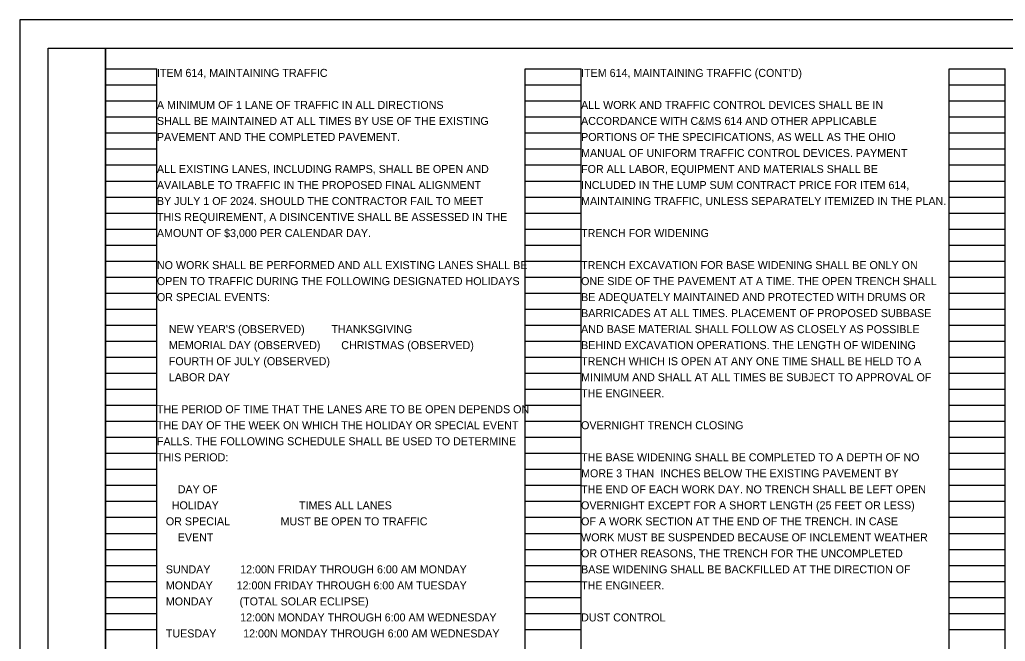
# Model space of a CAD drawing. Extents: x 0 to 34, y 0 to 22.
# Drawn here: x 0 to 17.24, y 11.13 to 22 of the extents above; entities that cross this region are included whole.
import ezdxf

# ---------------------------------------------------------------- set-up
doc = ezdxf.new("R2010")
doc.units = 0
for name, color, linetype in [('SC_Scratch1', 7, 'Continuous'), ('SH_Border', 7, 'Continuous'), ('SH_Cut_Line', 7, 'Continuous'), ('SH_Text', 7, 'Continuous')]:
    doc.layers.add(name, color=color, linetype=linetype)

msp = doc.modelspace()

# ---------------------------------------------------------------- linework, layer by layer
at = {"layer": 'SC_Scratch1'}
for p, q in [((1.5, 0.98), (1.5, 21.14)), ((1.5, 21.14), (2.4, 21.14)), ((2.4, 0.98), (2.4, 21.14)), ((8.84, 0.98), (8.84, 21.14)), ((8.84, 21.14), (9.82, 21.14)), ((9.82, 0.98), (9.82, 21.14)), ((16.26, 0.98), (16.26, 21.14)), ((16.26, 21.14), (17.24, 21.14)), ((17.24, 0.98), (17.24, 21.14)), ((1.5, 20.86), (2.4, 20.86)), ((8.84, 20.86), (9.82, 20.86)), ((16.26, 20.86), (17.24, 20.86)), ((1.5, 20.58), (2.4, 20.58)), ((8.84, 20.58), (9.82, 20.58)), ((16.26, 20.58), (17.24, 20.58)), ((1.5, 20.3), (2.4, 20.3)), ((8.84, 20.3), (9.82, 20.3)), ((16.26, 20.3), (17.24, 20.3)), ((1.5, 20.02), (2.4, 20.02)), ((8.84, 20.02), (9.82, 20.02)), ((16.26, 20.02), (17.24, 20.02)), ((1.5, 19.74), (2.4, 19.74)), ((8.84, 19.74), (9.82, 19.74)), ((16.26, 19.74), (17.24, 19.74)), ((1.5, 19.46), (2.4, 19.46)), ((8.84, 19.46), (9.82, 19.46)), ((16.26, 19.46), (17.24, 19.46)), ((1.5, 19.18), (2.4, 19.18)), ((8.84, 19.18), (9.82, 19.18)), ((16.26, 19.18), (17.24, 19.18)), ((1.5, 18.9), (2.4, 18.9)), ((8.84, 18.9), (9.82, 18.9)), ((16.26, 18.9), (17.24, 18.9)), ((1.5, 18.62), (2.4, 18.62)), ((8.84, 18.62), (9.82, 18.62)), ((16.26, 18.62), (17.24, 18.62)), ((1.5, 18.34), (2.4, 18.34)), ((8.84, 18.34), (9.82, 18.34)), ((16.26, 18.34), (17.24, 18.34)), ((1.5, 18.06), (2.4, 18.06)), ((8.84, 18.06), (9.82, 18.06)), ((16.26, 18.06), (17.24, 18.06)), ((1.5, 17.78), (2.4, 17.78)), ((8.84, 17.78), (9.82, 17.78)), ((16.26, 17.78), (17.24, 17.78)), ((1.5, 17.5), (2.4, 17.5)), ((8.84, 17.5), (9.82, 17.5)), ((16.26, 17.5), (17.24, 17.5)), ((1.5, 17.22), (2.4, 17.22)), ((8.84, 17.22), (9.82, 17.22)), ((16.26, 17.22), (17.24, 17.22)), ((1.5, 16.94), (2.4, 16.94)), ((8.84, 16.94), (9.82, 16.94)), ((16.26, 16.94), (17.24, 16.94)), ((1.5, 16.66), (2.4, 16.66)), ((8.84, 16.66), (9.82, 16.66)), ((16.26, 16.66), (17.24, 16.66)), ((1.5, 16.38), (2.4, 16.38)), ((8.84, 16.38), (9.82, 16.38)), ((16.26, 16.38), (17.24, 16.38)), ((1.5, 16.1), (2.4, 16.1)), ((8.84, 16.1), (9.82, 16.1)), ((16.26, 16.1), (17.24, 16.1)), ((1.5, 15.82), (2.4, 15.82)), ((8.84, 15.82), (9.82, 15.82)), ((16.26, 15.82), (17.24, 15.82)), ((1.5, 15.54), (2.4, 15.54)), ((8.84, 15.54), (9.82, 15.54)), ((16.26, 15.54), (17.24, 15.54)), ((1.5, 15.26), (2.4, 15.26)), ((8.84, 15.26), (9.82, 15.26)), ((16.26, 15.26), (17.24, 15.26)), ((1.5, 14.98), (2.4, 14.98)), ((8.84, 14.98), (9.82, 14.98)), ((16.26, 14.98), (17.24, 14.98)), ((1.5, 14.7), (2.4, 14.7)), ((8.84, 14.7), (9.82, 14.7)), ((16.26, 14.7), (17.24, 14.7)), ((1.5, 14.42), (2.4, 14.42)), ((8.84, 14.42), (9.82, 14.42)), ((16.26, 14.42), (17.24, 14.42)), ((1.5, 14.14), (2.4, 14.14)), ((8.84, 14.14), (9.82, 14.14)), ((16.26, 14.14), (17.24, 14.14)), ((1.5, 13.86), (2.4, 13.86)), ((8.84, 13.86), (9.82, 13.86)), ((16.26, 13.86), (17.24, 13.86)), ((1.5, 13.58), (2.4, 13.58)), ((8.84, 13.58), (9.82, 13.58)), ((16.26, 13.58), (17.24, 13.58)), ((1.5, 13.3), (2.4, 13.3)), ((8.84, 13.3), (9.82, 13.3)), ((16.26, 13.3), (17.24, 13.3)), ((1.5, 13.02), (2.4, 13.02)), ((8.84, 13.02), (9.82, 13.02)), ((16.26, 13.02), (17.24, 13.02)), ((1.5, 12.74), (2.4, 12.74)), ((8.84, 12.74), (9.82, 12.74)), ((16.26, 12.74), (17.24, 12.74)), ((1.5, 12.46), (2.4, 12.46)), ((8.84, 12.46), (9.82, 12.46)), ((16.26, 12.46), (17.24, 12.46)), ((1.5, 12.18), (2.4, 12.18)), ((8.84, 12.18), (9.82, 12.18)), ((16.26, 12.18), (17.24, 12.18)), ((1.5, 11.9), (2.4, 11.9)), ((8.84, 11.9), (9.82, 11.9)), ((16.26, 11.9), (17.24, 11.9)), ((1.5, 11.62), (2.4, 11.62)), ((8.84, 11.62), (9.82, 11.62)), ((16.26, 11.62), (17.24, 11.62)), ((1.5, 11.34), (2.4, 11.34)), ((8.84, 11.34), (9.82, 11.34)), ((16.26, 11.34), (17.24, 11.34))]:
    msp.add_line(p, q, dxfattribs=at)
at = {"layer": 'SH_Border'}
for points in [[(0.5, 21.5), (1.5, 21.5), (1.5, 0.5), (0.5, 0.5)], [(1.5, 21.5), (33.5, 21.5), (33.5, 0.5), (1.5, 0.5)]]:
    msp.add_lwpolyline(points, close=True, dxfattribs=at)
at = {"layer": 'SH_Cut_Line'}
msp.add_lwpolyline([(0, 0), (34, 0), (34, 22), (0, 22)], close=True, dxfattribs=at)

# ---------------------------------------------------------------- texts
at = {"layer": 'SH_Text'}
for s, p in [('ITEM 614, MAINTAINING TRAFFIC', (2.4, 21)), ("ITEM 614, MAINTAINING TRAFFIC (CONT'D)", (9.82, 21)), ('A MINIMUM OF 1 LANE OF TRAFFIC IN ALL DIRECTIONS', (2.4, 20.44)), ('ALL WORK AND TRAFFIC CONTROL DEVICES SHALL BE IN', (9.82, 20.44)), ('SHALL BE MAINTAINED AT ALL TIMES BY USE OF THE EXISTING', (2.4, 20.16)), ('ACCORDANCE WITH C&MS 614 AND OTHER APPLICABLE', (9.82, 20.16)), ('PAVEMENT AND THE COMPLETED PAVEMENT.', (2.4, 19.88)), ('PORTIONS OF THE SPECIFICATIONS, AS WELL AS THE OHIO', (9.82, 19.88)), ('MANUAL OF UNIFORM TRAFFIC CONTROL DEVICES. PAYMENT', (9.82, 19.6)), ('ALL EXISTING LANES, INCLUDING RAMPS, SHALL BE OPEN AND', (2.4, 19.32)), ('FOR ALL LABOR, EQUIPMENT AND MATERIALS SHALL BE', (9.82, 19.32)), ('AVAILABLE TO TRAFFIC IN THE PROPOSED FINAL ALIGNMENT', (2.4, 19.04)), ('INCLUDED IN THE LUMP SUM CONTRACT PRICE FOR ITEM 614,', (9.82, 19.04)), ('BY JULY 1 OF 2024. SHOULD THE CONTRACTOR FAIL TO MEET', (2.4, 18.76)), ('MAINTAINING TRAFFIC, UNLESS SEPARATELY ITEMIZED IN THE PLAN.', (9.82, 18.76)), ('THIS REQUIREMENT, A DISINCENTIVE SHALL BE ASSESSED IN THE', (2.4, 18.48)), ('AMOUNT OF $3,000 PER CALENDAR DAY.', (2.4, 18.2)), ('TRENCH FOR WIDENING', (9.82, 18.2)), ('NO WORK SHALL BE PERFORMED AND ALL EXISTING LANES SHALL BE', (2.4, 17.64)), ('TRENCH EXCAVATION FOR BASE WIDENING SHALL BE ONLY ON', (9.82, 17.64)), ('OPEN TO TRAFFIC DURING THE FOLLOWING DESIGNATED HOLIDAYS', (2.4, 17.36)), ('ONE SIDE OF THE PAVEMENT AT A TIME. THE OPEN TRENCH SHALL', (9.82, 17.36)), ('OR SPECIAL EVENTS:', (2.4, 17.08)), ('BE ADEQUATELY MAINTAINED AND PROTECTED WITH DRUMS OR', (9.82, 17.08)), ('BARRICADES AT ALL TIMES. PLACEMENT OF PROPOSED SUBBASE', (9.82, 16.8)), ("    NEW YEAR'S (OBSERVED)         THANKSGIVING   ", (2.4, 16.52)), ('AND BASE MATERIAL SHALL FOLLOW AS CLOSELY AS POSSIBLE', (9.82, 16.52)), ('    MEMORIAL DAY (OBSERVED)       CHRISTMAS (OBSERVED)', (2.4, 16.24)), ('BEHIND EXCAVATION OPERATIONS. THE LENGTH OF WIDENING', (9.82, 16.24)), ('    FOURTH OF JULY (OBSERVED)', (2.4, 15.96)), ('TRENCH WHICH IS OPEN AT ANY ONE TIME SHALL BE HELD TO A', (9.82, 15.96)), ('    LABOR DAY', (2.4, 15.68)), ('MINIMUM AND SHALL AT ALL TIMES BE SUBJECT TO APPROVAL OF', (9.82, 15.68)), ('THE ENGINEER.', (9.82, 15.4)), ('THE PERIOD OF TIME THAT THE LANES ARE TO BE OPEN DEPENDS ON', (2.4, 15.12)), ('THE DAY OF THE WEEK ON WHICH THE HOLIDAY OR SPECIAL EVENT', (2.4, 14.84)), ('OVERNIGHT TRENCH CLOSING', (9.82, 14.84)), ('FALLS. THE FOLLOWING SCHEDULE SHALL BE USED TO DETERMINE', (2.4, 14.56)), ('THIS PERIOD:', (2.4, 14.28)), ('THE BASE WIDENING SHALL BE COMPLETED TO A DEPTH OF NO', (9.82, 14.28)), ('MORE 3 THAN  INCHES BELOW THE EXISTING PAVEMENT BY', (9.82, 14)), ('       DAY OF', (2.4, 13.72)), ('THE END OF EACH WORK DAY. NO TRENCH SHALL BE LEFT OPEN', (9.82, 13.72)), ('     HOLIDAY                           TIMES ALL LANES', (2.4, 13.44)), ('OVERNIGHT EXCEPT FOR A SHORT LENGTH (25 FEET OR LESS)', (9.82, 13.44)), ('   OR SPECIAL                 MUST BE OPEN TO TRAFFIC', (2.4, 13.16)), ('OF A WORK SECTION AT THE END OF THE TRENCH. IN CASE', (9.82, 13.16)), ('       EVENT', (2.4, 12.88)), ('WORK MUST BE SUSPENDED BECAUSE OF INCLEMENT WEATHER', (9.82, 12.88)), ('OR OTHER REASONS, THE TRENCH FOR THE UNCOMPLETED', (9.82, 12.6)), ('   SUNDAY          12:00N FRIDAY THROUGH 6:00 AM MONDAY', (2.4, 12.32)), ('BASE WIDENING SHALL BE BACKFILLED AT THE DIRECTION OF', (9.82, 12.32)), ('   MONDAY        12:00N FRIDAY THROUGH 6:00 AM TUESDAY', (2.4, 12.04)), ('THE ENGINEER.', (9.82, 12.04)), ('   MONDAY         (TOTAL SOLAR ECLIPSE)', (2.4, 11.76)), ('                            12:00N MONDAY THROUGH 6:00 AM WEDNESDAY', (2.4, 11.48)), ('DUST CONTROL', (9.82, 11.48)), ('   TUESDAY         12:00N MONDAY THROUGH 6:00 AM WEDNESDAY', (2.4, 11.2))]:
    msp.add_text(s, height=0.14, dxfattribs=at).set_placement(p)

doc.saveas('drawing.dxf')
